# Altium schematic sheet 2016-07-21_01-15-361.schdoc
size 351 x 172 mm; SheetNumber: 1; SheetTotal: 1
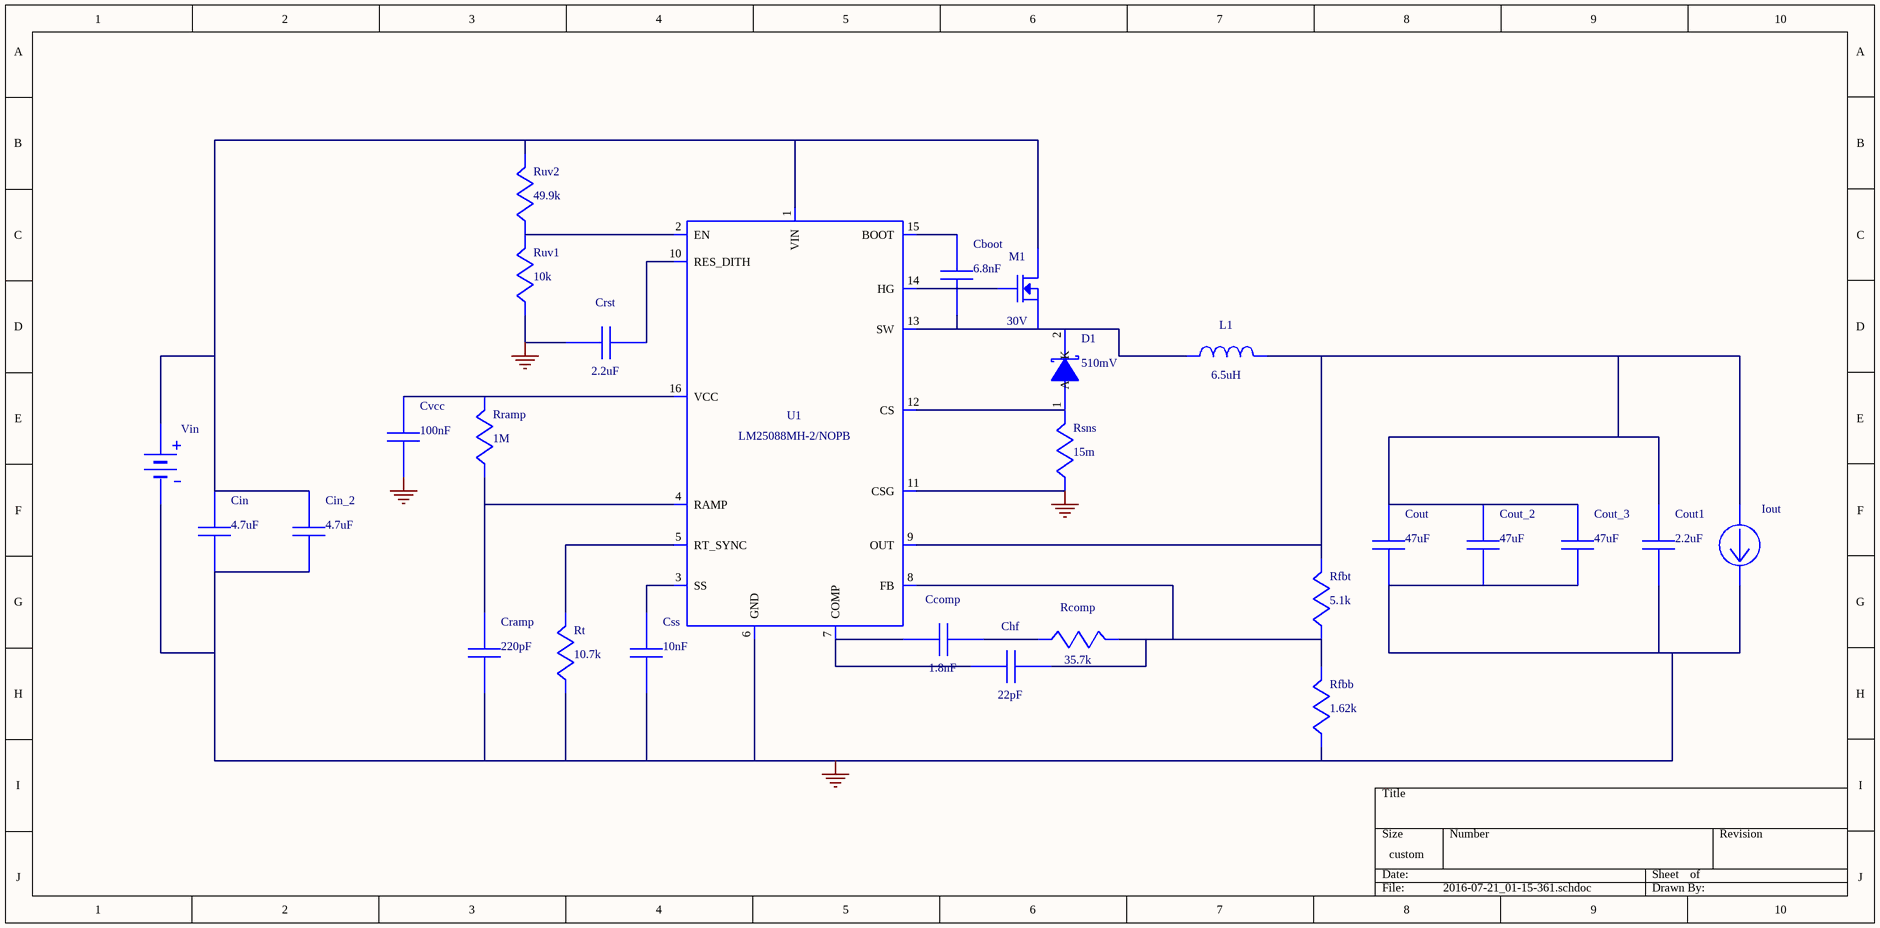
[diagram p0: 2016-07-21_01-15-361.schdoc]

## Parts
Cboot  value 6.8nF  (hidden comment: C0603C682K5RACTU)
Ccomp  value 1.8nF  (hidden comment: GRM1885C1H182JA01J)
Chf  value 22pF  (hidden comment: C0603C220K3GACTU)
Cin  value 4.7uF  (hidden comment: GRM31CR71H475KA12L)
Cin_2  value 4.7uF  (hidden comment: GRM31CR71H475KA12L)
Cout  value 47uF  (hidden comment: GRM31CR61A476KE15L)
Cout1  value 2.2uF  (hidden comment: GRM155R60J225ME15D)
Cout_2  value 47uF  (hidden comment: GRM31CR61A476KE15L)
Cout_3  value 47uF  (hidden comment: GRM31CR61A476KE15L)
Cramp  value 220pF  (hidden comment: 06033A220JAT2A)
Crst  value 2.2uF  (hidden comment: C0603C225K9PACTU)
Css  value 10nF  (hidden comment: C0603C103J5RACTU)
Cvcc  value 100nF  (hidden comment: C0603C104K3RACTU)
D1  value 510mV  (hidden comment: 50WQ04FNPBF)
Iout  WB_CURRENT_LOAD  (value not drawn)
L1  value 6.5uH  (hidden comment: SRR1208-6R5ML)
M1  value 30V  (hidden comment: CSD17308Q3)
Rcomp  value 35.7k  (hidden comment: CRCW060335K7FKEA)
Rfbb  value 1.62k  (hidden comment: CRCW04021K62FKED)
Rfbt  value 5.1k  (hidden comment: RC0603FR-075K1L)
Rramp  value 1M  (hidden comment: CRCW06031M00FKEA)
Rsns  value 15m  (hidden comment: CSR1206FK15L0)
Rt  value 10.7k  (hidden comment: CRCW060310K7FKEA)
Ruv1  value 10k  (hidden comment: ERJ-6ENF1002V)
Ruv2  value 49.9k  (hidden comment: ERJ-6ENF4992V)
U1  LM5088MH-2  (value not drawn)
Vin  WB_BATTERY  (value not drawn)

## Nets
0: Cin.2 Cin_2.2 Cout.2 Cout1.2 Cout_2.2 Cout_3.2 Cramp.2 Crst.1 Css.2 Cvcc.2 Iout.2(-) Rfbb.2 Rsns.2 Rt.2 Ruv1.2 U1.6(GND) U1.11(CSG) U1.17(EP) Vin.2(-)
NetCboot_1: Cboot.1 D1.2(K) L1.1 M1.1(Source) M1.2(Source) M1.3(Source) U1.13(SW)
NetCboot_2: Cboot.2 U1.15(BOOT)
NetCcomp_1: Ccomp.1 Rcomp.2
NetCcomp_2: Ccomp.2 Chf.1 U1.7(COMP)
NetChf_2: Chf.2 Rcomp.1 Rfbb.1 Rfbt.2 U1.8(FB)
NetCin_1: Cin.1 Cin_2.1 M1.5(Drain) M1.6(Drain) M1.7(Drain) M1.8(Drain) M1.9(Drain) Ruv2.1 U1.1(VIN) Vin.1(+)
NetCout_1: Cout.1 Cout1.1 Cout_2.1 Cout_3.1 Iout.1(+) L1.2 Rfbt.1 U1.9(OUT)
NetCramp_1: Cramp.1 Rramp.2 U1.4(RAMP)
NetCrst_2: Crst.2 U1.10(RES_DITH)
NetCss_1: Css.1 U1.3(SS)
NetCvcc_1: Cvcc.1 Rramp.1 U1.16(VCC)
NetD1_1: D1.1(A) D1.3(A) Rsns.1 U1.12(CS)
NetM1_4: M1.4(Gate) U1.14(HG)
NetRt_1: Rt.1 U1.5(RT_SYNC)
NetRuv1_1: Ruv1.1 Ruv2.2 U1.2(EN)

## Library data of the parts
Cboot = C0603C682K5RACTU: Manufacturer Name: Kemet
Ccomp = GRM1885C1H182JA01J: GRM1885C1H182JA0; Manufacturer Name: MuRata
Chf = C0603C220K3GACTU: Manufacturer Name: Kemet
Cin Cin_2 = GRM31CR71H475KA12L: GRM31CR71H475KA1; Manufacturer Name: MuRata
Cout Cout_2 Cout_3 = GRM31CR61A476KE15L: GRM31CR61A476KE1; Manufacturer Name: MuRata
Cout1 = GRM155R60J225ME15D: GRM155R60J225ME1; Manufacturer Name: MuRata
Cramp = 06033A220JAT2A: Manufacturer Name: AVX
Crst = C0603C225K9PACTU: Manufacturer Name: Kemet
Css = C0603C103J5RACTU: Manufacturer Name: Kemet
Cvcc = C0603C104K3RACTU: Manufacturer Name: Kemet
D1 = 50WQ04FNPBF: Manufacturer Name: Vishay-Semiconductor
L1 = SRR1208-6R5ML: Manufacturer Name: Bourns
M1 = CSD17308Q3: Manufacturer Name: Texas Instruments
Rcomp = CRCW060335K7FKEA: Manufacturer Name: Vishay-Dale
Rfbb = CRCW04021K62FKED: Manufacturer Name: Vishay-Dale
Rfbt = RC0603FR-075K1L: Manufacturer Name: Yageo America
Rramp = CRCW06031M00FKEA: Manufacturer Name: Vishay-Dale
Rsns = CSR1206FK15L0: Manufacturer Name: Stackpole Electronics Inc
Rt = CRCW060310K7FKEA: Manufacturer Name: Vishay-Dale
Ruv1 = ERJ-6ENF1002V: Manufacturer Name: Panasonic
Ruv2 = ERJ-6ENF4992V: Manufacturer Name: Panasonic
U1 = LM5088MH-2: LM25088MH-2/NOPB; Manufacturer Name: Texas Instruments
